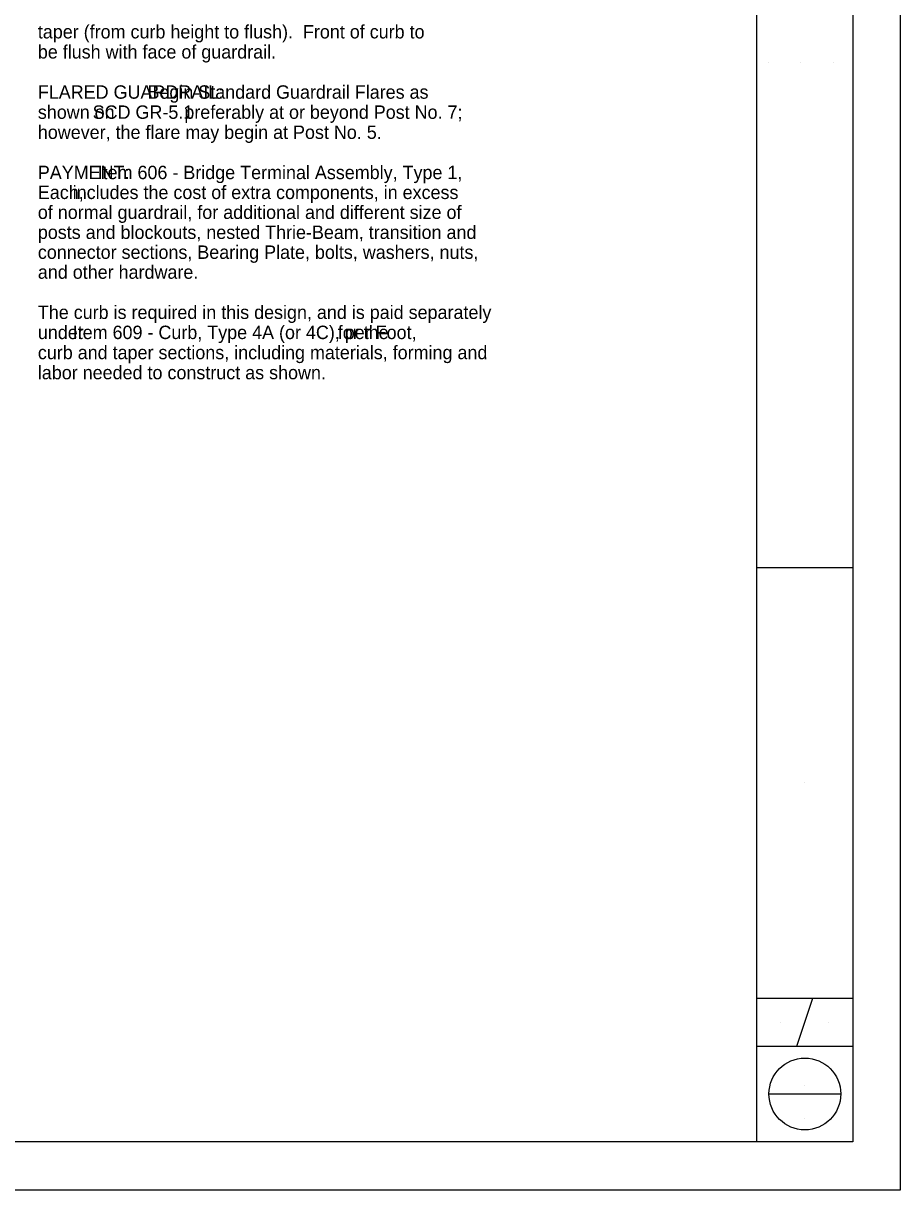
# Model space of a CAD drawing. Extents: x 0 to 34, y 0 to 22.
# Drawn here: x 24.84 to 34, y 0 to 12.19 of the extents above; entities that cross this region are included whole.
import ezdxf

# ---------------------------------------------------------------- set-up
doc = ezdxf.new("R2010")
doc.units = 0
for name, color, linetype in [('SH_Border', 7, 'Continuous'), ('SH_Cut_Line', 7, 'Continuous'), ('SH_Data', 7, 'Continuous'), ('ST_Text', 7, 'Continuous')]:
    doc.layers.add(name, color=color, linetype=linetype)

msp = doc.modelspace()

# ---------------------------------------------------------------- linework, layer by layer
at = {"layer": 'SH_Border'}
for p, q in [((32.5, 0.5), (32.5, 21.5)), ((32.5, 6.5), (33.5, 6.5)), ((32.5, 2), (33.5, 2)), ((32.917, 1.5), (33.083, 2)), ((32.5, 1.5), (33.5, 1.5))]:
    msp.add_line(p, q, dxfattribs=at)
msp.add_lwpolyline([(2, 21.5), (33.5, 21.5), (33.5, 0.5), (2, 0.5)], close=True, dxfattribs=at)
at = {"layer": 'SH_Cut_Line'}
msp.add_lwpolyline([(0, 0), (34, 0), (34, 22), (0, 22)], close=True, dxfattribs=at)
at = {"layer": 'SH_Data'}
for p, q in [((32.625, 11.775), (32.625, 11.775)), ((32.95, 11.775), (32.95, 11.775)), ((33.3, 11.775), (33.3, 11.775)), ((33, 4.25), (33, 4.25)), ((32.75, 1.75), (32.75, 1.75)), ((33.25, 1.75), (33.25, 1.75)), ((32.625, 1), (33.375, 1)), ((33, 1.085), (33, 1.085)), ((33, 0.745), (33, 0.745))]:
    msp.add_line(p, q, dxfattribs=at)
msp.add_circle((33, 1), 0.375, dxfattribs=at)

# ---------------------------------------------------------------- texts
at = {"layer": 'ST_Text'}
for s, p in [('taper (from curb height to flush).  Front of curb to ', (24.992, 12.028)), ('be flush with face of guardrail.', (24.992, 11.818)), ('FLARED GUARDRAIL: ', (24.992, 11.398)), ('                      Begin Standard Guardrail Flares as', (24.992, 11.398)), ('shown on              preferably at or beyond Post No. 7;', (24.992, 11.188)), ('           SCD GR-5.1', (24.992, 11.188)), ('however, the flare may begin at Post No. 5.', (24.992, 10.978)), ('PAYMENT:', (24.992, 10.558)), ('            Item 606 - Bridge Terminal Assembly, Type 1,', (24.992, 10.558)), ('Each,', (24.992, 10.35)), ('       includes the cost of extra components, in excess', (24.992, 10.35)), ('of normal guardrail, for additional and different size of', (24.992, 10.142)), ('posts and blockouts, nested Thrie-Beam, transition and', (24.992, 9.933)), ('connector sections, Bearing Plate, bolts, washers, nuts,', (24.992, 9.725)), ('and other hardware.', (24.992, 9.517)), ('The curb is required in this design, and is paid separately', (24.992, 9.097)), ('under                                                   for the', (24.992, 8.887)), ('       Item 609 - Curb, Type 4A (or 4C), per Foot,', (24.992, 8.887)), ('curb and taper sections, including materials, forming and', (24.992, 8.677)), ('labor needed to construct as shown.', (24.992, 8.467))]:
    msp.add_text(s, height=0.14, dxfattribs=at).set_placement(p)

doc.saveas('drawing.dxf')
